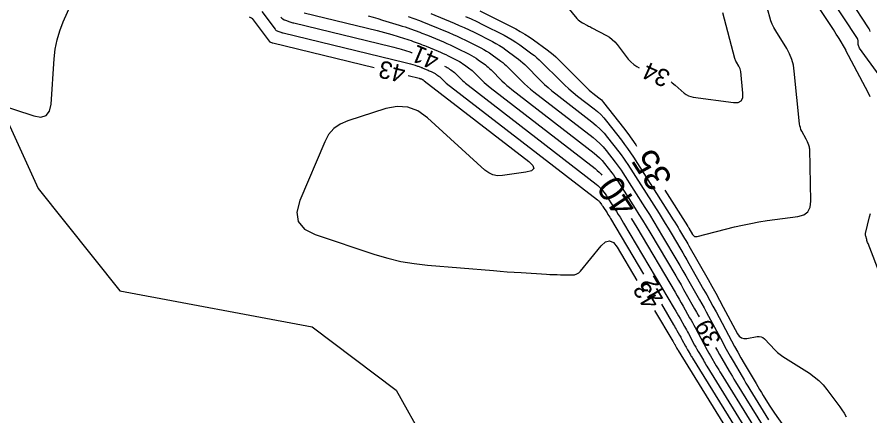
# Model space of a CAD drawing. Extents: x 2384780 to 2405861, y 547869 to 573706.
# Drawn here: x 2390194.3 to 2390291.8, y 552348.1 to 552393.7 of the extents above; entities that cross this region are included whole.
import ezdxf

# ---------------------------------------------------------------- set-up
doc = ezdxf.new("R2010")
doc.units = 0
for name, color, linetype in [('Old_Level_60', 7, 'Continuous'), ('Old_Level_61', 7, 'Continuous'), ('Prop Buffer Zone 1', 7, 'Continuous')]:
    doc.layers.add(name, color=color, linetype=linetype)

msp = doc.modelspace()

# ---------------------------------------------------------------- linework, layer by layer
at = {"layer": 'Old_Level_60'}
for points in [[(2390291.862, 552392.0805), (2390291.8245, 552392.235), (2390291.766, 552392.383), (2390291.68675, 552392.52425), (2390289.58125, 552395.76625), (2390289.148, 552396.47025), (2390288.75025, 552397.19275), (2390288.38825, 552397.93375), (2390288.06175, 552398.69325), (2390286.382, 552402.87975), (2390286.2985, 552403.07075), (2390286.2045, 552403.2555), (2390286.09925, 552403.43425), (2390285.983, 552403.607), (2390285.58575, 552404.16175), (2390285.4995, 552404.27975), (2390285.41075, 552404.39575), (2390285.31975, 552404.51), (2390285.2265, 552404.62275)], [(2390191.8935, 552383.839), (2390196.21325, 552382.43025), (2390197.0315, 552382.2875), (2390197.63425, 552382.463), (2390198.022, 552382.957), (2390198.1945, 552383.76925), (2390198.541, 552388.9505), (2390198.6625, 552390.049), (2390198.878, 552391.12425), (2390199.18775, 552392.1765), (2390199.59175, 552393.20525), (2390202.20475, 552399.098)], [(2390291.86625, 552384.6), (2390291.74275, 552384.873), (2390291.6145, 552385.1435), (2390291.48175, 552385.41175), (2390291.344, 552385.6775), (2390289.09575, 552389.92975), (2390289.08975, 552389.9425), (2390289.085, 552389.95575), (2390289.08175, 552389.9695), (2390289.0795, 552389.9835), (2390289.075, 552390.03), (2390289.0735, 552390.03975), (2390289.07075, 552390.049), (2390289.06725, 552390.05825), (2390289.0625, 552390.06675), (2390288.317, 552391.275), (2390288.1565, 552391.5335), (2390287.9945, 552391.791), (2390287.83125, 552392.0475), (2390287.66625, 552392.303), (2390284.72025, 552396.83875)], [(2390256.70725, 552395.53525), (2390258.333, 552393.585), (2390258.46975, 552393.4365), (2390258.619, 552393.30375), (2390258.781, 552393.187), (2390258.9555, 552393.08575), (2390259.54675, 552392.78125), (2390259.67325, 552392.71575), (2390259.79975, 552392.65), (2390259.926, 552392.58375), (2390260.052, 552392.51725), (2390261.7245, 552391.6325), (2390262.069, 552391.4265), (2390262.38525, 552391.18725), (2390262.67375, 552390.91475), (2390262.934, 552390.60925), (2390264.21225, 552388.938), (2390264.504, 552388.60325), (2390264.8315, 552388.315), (2390265.195, 552388.07375), (2390265.46225, 552387.94325)], [(2390292.88875, 552387.07025), (2390290.6635, 552390.18075), (2390290.6035, 552390.2785), (2390290.55925, 552390.38175), (2390290.531, 552390.49025), (2390290.5185, 552390.60425), (2390290.504, 552390.98575), (2390290.49575, 552391.06575), (2390290.47725, 552391.1425), (2390290.44825, 552391.216), (2390290.40875, 552391.28625), (2390287.2375, 552396.169)], [(2390222.3085, 552394.3815), (2390223.80925, 552392.364), (2390223.87725, 552392.285), (2390223.95425, 552392.21875), (2390224.0405, 552392.165), (2390224.136, 552392.1235)], [(2390220.86625, 552393.7505), (2390220.91775, 552393.72875)], [(2390220.91775, 552393.72875), (2390221.08625, 552393.6595), (2390221.12075, 552393.6425), (2390221.15225, 552393.6215), (2390221.18025, 552393.5965), (2390221.20525, 552393.567), (2390223.12925, 552390.98025), (2390223.16, 552390.9445), (2390223.195, 552390.9145), (2390223.234, 552390.89025), (2390223.27725, 552390.8715), (2390223.425, 552390.8195), (2390223.457, 552390.80875), (2390223.489, 552390.799), (2390223.52125, 552390.78975), (2390223.55375, 552390.7815), (2390235.1455, 552387.97725)], [(2390224.48925, 552393.7475), (2390224.59425, 552393.6255), (2390224.7135, 552393.523), (2390224.847, 552393.43975), (2390224.99475, 552393.37575), (2390225.5005, 552393.19825), (2390225.60925, 552393.1615), (2390225.71875, 552393.12775), (2390225.82925, 552393.0965), (2390225.9405, 552393.06825), (2390237.0975, 552390.369), (2390237.3855, 552390.297), (2390237.67225, 552390.221), (2390237.95775, 552390.14075), (2390238.24225, 552390.05625), (2390239.229, 552389.75525), (2390239.3975, 552389.7025), (2390239.49, 552389.67225)], [(2390234.46175, 552393.86625), (2390235.016, 552393.71925), (2390235.56775, 552393.56425), (2390236.1175, 552393.401), (2390238.02425, 552392.8195), (2390238.35, 552392.71775), (2390238.67425, 552392.61125), (2390238.997, 552392.50025), (2390239.31825, 552392.38475), (2390240.36475, 552391.99975), (2390240.58875, 552391.916), (2390240.8115, 552391.83025), (2390241.03375, 552391.742), (2390241.25475, 552391.65175)], [(2390239.028, 552393.81175), (2390240.32725, 552393.334), (2390240.605, 552393.23025), (2390240.88175, 552393.12375), (2390241.15725, 552393.01425), (2390241.432, 552392.902), (2390243.685, 552391.968), (2390244.16575, 552391.76325), (2390244.6425, 552391.55), (2390245.115, 552391.32775), (2390245.58375, 552391.0965), (2390247.3505, 552390.20475), (2390247.68425, 552390.0275), (2390248.01, 552389.837), (2390248.3275, 552389.6335), (2390248.637, 552389.4165), (2390249.6345, 552388.686), (2390249.84475, 552388.5255), (2390250.0485, 552388.35725), (2390250.24575, 552388.18125), (2390250.43625, 552387.99775), (2390251.993, 552386.43725), (2390252.33175, 552386.1085), (2390252.68025, 552385.791), (2390253.039, 552385.485), (2390253.4075, 552385.19025), (2390260.1775, 552379.9535), (2390260.5845, 552379.618), (2390260.968, 552379.25925), (2390261.32825, 552378.87725), (2390261.66525, 552378.472), (2390262.7285, 552377.1095), (2390262.95275, 552376.81475), (2390263.1695, 552376.51525), (2390263.37925, 552376.2105), (2390263.58175, 552375.9005), (2390266.0985, 552371.946), (2390266.61925, 552371.1205), (2390267.13325, 552370.29075), (2390267.64075, 552369.45725), (2390268.1415, 552368.61925), (2390269.7665, 552365.876), (2390270.1135, 552365.28725), (2390270.45775, 552364.69725), (2390270.7995, 552364.1055), (2390271.13875, 552363.5125), (2390272.36075, 552361.3645), (2390272.621, 552360.9035), (2390272.87825, 552360.4405), (2390273.13225, 552359.976), (2390273.38325, 552359.50975), (2390274.967, 552356.543), (2390275.2645, 552355.992), (2390275.56725, 552355.444), (2390275.8755, 552354.899), (2390276.189, 552354.35675), (2390277.2215, 552352.59075), (2390277.444, 552352.213), (2390277.6685, 552351.8365), (2390277.8955, 552351.46125), (2390278.1245, 552351.08775), (2390280.2565, 552347.6335)], [(2390241.609, 552394.1525), (2390244.3, 552393.03675), (2390244.874, 552392.7925), (2390245.4435, 552392.5375), (2390246.008, 552392.272), (2390246.56775, 552391.996), (2390248.678, 552390.93075), (2390249.07675, 552390.71925), (2390249.4655, 552390.49175), (2390249.845, 552390.2485), (2390250.2145, 552389.98925), (2390251.40575, 552389.11675), (2390251.657, 552388.92525), (2390251.9005, 552388.72425), (2390252.13575, 552388.51425), (2390252.36325, 552388.29475), (2390254.22275, 552386.431), (2390254.62725, 552386.03825), (2390255.04375, 552385.65925), (2390255.472, 552385.29375), (2390255.91225, 552384.94175), (2390260.05325, 552381.7385), (2390260.54275, 552381.335), (2390261.004, 552380.9035), (2390261.4375, 552380.444), (2390261.843, 552379.95625), (2390263.12175, 552378.3175), (2390263.3915, 552377.96325), (2390263.6525, 552377.60275), (2390263.9045, 552377.23625), (2390264.14825, 552376.8635), (2390267.7265, 552371.24075), (2390268.07925, 552370.68175), (2390268.42725, 552370.11975), (2390268.771, 552369.55525), (2390269.11, 552368.98775), (2390270.2105, 552367.13), (2390270.4455, 552366.73125), (2390270.67875, 552366.33175), (2390270.91, 552365.931), (2390271.13975, 552365.5295), (2390272.82925, 552362.55975), (2390273.18925, 552361.92225), (2390273.54475, 552361.28225), (2390273.896, 552360.64), (2390274.243, 552359.99525), (2390276.02275, 552356.66175), (2390276.3755, 552356.00825), (2390276.7345, 552355.3585), (2390277.1, 552354.712), (2390277.47175, 552354.06925), (2390278.8195, 552351.76375), (2390279.02125, 552351.42125), (2390279.22475, 552351.08), (2390279.4305, 552350.74), (2390279.63825, 552350.40125), (2390280.32, 552349.2965), (2390280.468, 552349.06125), (2390280.61975, 552348.82825), (2390280.77525, 552348.59775), (2390280.9345, 552348.36975), (2390283.79275, 552344.3515)], [(2390245.5825, 552393.8215), (2390246.2445, 552393.525), (2390246.901, 552393.21625), (2390247.55175, 552392.8955), (2390250.00525, 552391.657), (2390250.469, 552391.41075), (2390250.92125, 552391.1465), (2390251.36225, 552390.8635), (2390251.792, 552390.562), (2390253.177, 552389.54775), (2390253.46925, 552389.32475), (2390253.75225, 552389.09125), (2390254.026, 552388.847), (2390254.2905, 552388.592), (2390256.4525, 552386.42475), (2390256.92275, 552385.96825), (2390257.407, 552385.5275), (2390257.905, 552385.1025), (2390258.417, 552384.69325), (2390260.299, 552383.2375), (2390260.691, 552382.91425), (2390261.06075, 552382.5685), (2390261.408, 552382.20025), (2390261.73275, 552381.8095), (2390263.42875, 552379.636), (2390263.78625, 552379.16625), (2390264.1325, 552378.68825), (2390264.467, 552378.20225), (2390264.78975, 552377.70775), (2390269.3545, 552370.5355), (2390269.539, 552370.24275), (2390269.72125, 552369.94875), (2390269.901, 552369.65325), (2390270.0785, 552369.3565), (2390270.6545, 552368.384), (2390270.7775, 552368.1755), (2390270.8995, 552367.96625), (2390271.02075, 552367.7565), (2390271.14075, 552367.54625), (2390273.3305, 552363.69775), (2390273.77375, 552362.9125), (2390274.21175, 552362.12425), (2390274.64425, 552361.333), (2390275.07175, 552360.539)], [(2390269.10475, 552386.3075), (2390269.24225, 552386.2145), (2390269.57075, 552385.9505), (2390270.614, 552385.04025), (2390270.84625, 552384.86475), (2390271.09625, 552384.72825), (2390271.364, 552384.63075), (2390271.64925, 552384.5725), (2390276.24125, 552383.96525), (2390276.76175, 552383.97125), (2390277.116, 552384.1485), (2390277.30425, 552384.497), (2390277.3265, 552385.01675), (2390277.07675, 552387.512), (2390277.05125, 552387.67425), (2390277.00825, 552387.8305), (2390276.9475, 552387.98075), (2390276.86925, 552388.125), (2390276.5845, 552388.5865), (2390276.5275, 552388.687), (2390276.478, 552388.791), (2390276.4365, 552388.89825), (2390276.40275, 552389.00875), (2390275.01725, 552394.21275)], [(2390224.136, 552392.1235), (2390224.46275, 552392.009), (2390224.533, 552391.98525), (2390224.604, 552391.96325), (2390224.67525, 552391.94325), (2390224.747, 552391.92475), (2390238.6935, 552388.55075), (2390238.84725, 552388.5125), (2390239.00025, 552388.47175), (2390239.15275, 552388.429), (2390239.3045, 552388.38375), (2390239.83125, 552388.22325), (2390239.92125, 552388.195), (2390240.011, 552388.16575), (2390240.1, 552388.135), (2390240.18875, 552388.103), (2390240.47775, 552387.99675), (2390240.53975, 552387.97375), (2390240.60125, 552387.95), (2390240.6625, 552387.92575), (2390240.72375, 552387.90075), (2390241.225, 552387.69275), (2390241.332, 552387.64725), (2390241.43825, 552387.59975), (2390241.5435, 552387.55025), (2390241.64775, 552387.49875), (2390242.041, 552387.30025), (2390242.11525, 552387.261), (2390242.18775, 552387.2185), (2390242.25825, 552387.17325), (2390242.32725, 552387.125), (2390242.54925, 552386.96225), (2390242.596, 552386.92675), (2390242.64125, 552386.88925), (2390242.68525, 552386.85), (2390242.7275, 552386.80925), (2390243.074, 552386.462), (2390243.1495, 552386.38875), (2390243.227, 552386.318), (2390243.30675, 552386.25), (2390243.38875, 552386.1845), (2390260.6745, 552372.81325), (2390260.75125, 552372.75), (2390260.8235, 552372.6825), (2390260.8915, 552372.6105), (2390260.955, 552372.534), (2390261.15525, 552372.27725), (2390261.1975, 552372.22175), (2390261.2385, 552372.16525), (2390261.278, 552372.10775), (2390261.31625, 552372.0495), (2390261.7865, 552371.3105), (2390261.88675, 552371.15175), (2390261.9855, 552370.992), (2390262.083, 552370.83175), (2390262.1795, 552370.67075), (2390265.95475, 552364.297)], [(2390241.25475, 552391.65175), (2390243.07, 552390.89925), (2390243.45725, 552390.73425), (2390243.84125, 552390.5625), (2390244.22225, 552390.38325), (2390244.59975, 552390.19725), (2390246.02325, 552389.47875), (2390246.292, 552389.336), (2390246.5545, 552389.1825), (2390246.81025, 552389.01825), (2390247.0595, 552388.8435), (2390247.86325, 552388.255), (2390248.03275, 552388.12575), (2390248.19675, 552387.99025), (2390248.3555, 552387.8485), (2390248.509, 552387.7005), (2390249.76325, 552386.44325), (2390250.03625, 552386.1785), (2390250.317, 552385.92275), (2390250.606, 552385.67625), (2390250.903, 552385.43875), (2390260.30175, 552378.1685), (2390260.626, 552377.901), (2390260.93175, 552377.61525), (2390261.219, 552377.3105), (2390261.48775, 552376.9875), (2390262.33525, 552375.90125), (2390262.514, 552375.6665), (2390262.68675, 552375.42775), (2390262.854, 552375.18475), (2390263.01525, 552374.93775), (2390265.0045, 552371.81225), (2390265.428, 552371.14075), (2390265.84625, 552370.466), (2390266.259, 552369.788), (2390266.66625, 552369.1065), (2390269.63425, 552364.09575), (2390269.938, 552363.5805), (2390270.23925, 552363.064), (2390270.5385, 552362.546), (2390270.83525, 552362.027), (2390271.8015, 552360.32875), (2390272.00725, 552359.96425), (2390272.2105, 552359.59825), (2390272.30925, 552359.418)], [(2390243.17425, 552388.1245), (2390243.36825, 552388.0265), (2390243.5075, 552387.9525), (2390243.64325, 552387.87325), (2390243.77575, 552387.78825), (2390243.90475, 552387.69775), (2390244.3205, 552387.39325), (2390244.40825, 552387.32625), (2390244.49325, 552387.25625), (2390244.57525, 552387.183), (2390244.65475, 552387.10625), (2390245.30375, 552386.45575), (2390245.445, 552386.31875), (2390245.59025, 552386.18625), (2390245.73975, 552386.05875), (2390245.8935, 552385.936), (2390260.55025, 552374.59825), (2390260.7095, 552374.467), (2390260.85975, 552374.32675), (2390261.00075, 552374.17725), (2390261.1325, 552374.0185), (2390261.54875, 552373.48525), (2390261.63625, 552373.37), (2390261.72125, 552373.25275), (2390261.80325, 552373.1335), (2390261.8825, 552373.01225), (2390262.85925, 552371.47775), (2390263.06725, 552371.148), (2390263.2725, 552370.81675), (2390263.475, 552370.48375), (2390263.675, 552370.14925), (2390269.474, 552360.359), (2390269.63925, 552360.079), (2390269.803, 552359.798), (2390269.96575, 552359.5165), (2390270.12725, 552359.234), (2390270.6525, 552358.3105), (2390270.7645, 552358.11225), (2390270.875, 552357.91325), (2390270.98425, 552357.71375), (2390271.09225, 552357.51325), (2390271.79975, 552356.1875), (2390271.9315, 552355.9435), (2390272.06575, 552355.701), (2390272.20225, 552355.4595), (2390272.341, 552355.2195), (2390272.79825, 552354.4375), (2390272.8965, 552354.27025), (2390272.996, 552354.1035), (2390273.0965, 552353.9375), (2390273.198, 552353.772), (2390282.35925, 552338.92925)], [(2390239.0335, 552387.0365), (2390240.2895, 552386.73275), (2390240.309, 552386.72775), (2390240.3285, 552386.72275), (2390240.34775, 552386.71725), (2390240.367, 552386.7115), (2390240.43375, 552386.69125), (2390240.445, 552386.6875), (2390240.4565, 552386.68375), (2390240.46775, 552386.68), (2390240.479, 552386.676), (2390240.5155, 552386.6625), (2390240.52325, 552386.6595), (2390240.53125, 552386.6565), (2390240.539, 552386.6535), (2390240.54675, 552386.65025), (2390240.61025, 552386.624), (2390240.62375, 552386.61825), (2390240.63725, 552386.61225), (2390240.6505, 552386.606), (2390240.66375, 552386.5995), (2390240.7135, 552386.57425), (2390240.723, 552386.56925), (2390240.732, 552386.564), (2390240.741, 552386.55825), (2390240.74975, 552386.552), (2390240.77775, 552386.5315), (2390240.78375, 552386.527), (2390240.7895, 552386.52225), (2390240.795, 552386.51725), (2390240.8005, 552386.512), (2390240.84425, 552386.468), (2390240.85375, 552386.45875), (2390240.86375, 552386.45), (2390240.87375, 552386.44125), (2390240.88425, 552386.433), (2390252.81725, 552377.20225), (2390253.288, 552376.74475), (2390253.38975, 552376.386), (2390253.1225, 552376.126), (2390252.48625, 552375.96475), (2390249.8055, 552375.5985), (2390249.24925, 552375.57875), (2390248.72975, 552375.67625), (2390248.2465, 552375.89125), (2390247.8, 552376.22325), (2390241.2325, 552382.21525), (2390240.159, 552382.989), (2390239.0105, 552383.42025), (2390237.787, 552383.50875), (2390236.4885, 552383.255), (2390232.1235, 552381.86575), (2390231.25725, 552381.49225), (2390230.5295, 552380.96725), (2390229.93975, 552380.29075), (2390229.48825, 552379.4625), (2390226.64025, 552372.728), (2390226.292, 552371.4035), (2390226.46775, 552370.3155), (2390227.168, 552369.4645), (2390228.392, 552368.85025), (2390235.2365, 552366.567), (2390236.7125, 552366.12275), (2390238.207, 552365.76875), (2390239.72, 552365.505), (2390241.2515, 552365.3315), (2390248.783, 552364.70375), (2390249.57475, 552364.64), (2390250.367, 552364.5805), (2390251.15975, 552364.5255), (2390251.9525, 552364.475), (2390254.83825, 552364.29875), (2390255.24575, 552364.27625), (2390255.65375, 552364.2585), (2390256.06175, 552364.2455), (2390256.47, 552364.237), (2390257.804, 552364.2175), (2390258.07675, 552364.2415), (2390258.32325, 552364.32175), (2390258.5435, 552364.4585), (2390258.73775, 552364.6515), (2390261.102, 552367.53825), (2390261.59625, 552367.9935), (2390262.06575, 552368.122), (2390262.5105, 552367.924), (2390262.93025, 552367.3995), (2390265.18525, 552363.5925)], [(2390295.614, 552357.4845), (2390291.629, 552367.8285), (2390291.58725, 552367.94), (2390291.54775, 552368.052), (2390291.51025, 552368.16475), (2390291.47475, 552368.27825), (2390291.36275, 552368.65025), (2390291.344, 552368.73), (2390291.33625, 552368.81025), (2390291.3395, 552368.89075), (2390291.3535, 552368.9715), (2390291.80825, 552370.85775), (2390291.89875, 552371.263)], [(2390267.22375, 552360.151), (2390269.31375, 552356.6225), (2390269.34025, 552356.57725), (2390269.36675, 552356.532), (2390269.393, 552356.48675), (2390269.419, 552356.44125), (2390269.5035, 552356.2925), (2390269.5215, 552356.2605), (2390269.5395, 552356.2285), (2390269.557, 552356.19625), (2390269.5745, 552356.164), (2390269.6885, 552355.9505), (2390269.7095, 552355.91125), (2390269.73125, 552355.872), (2390269.75325, 552355.83325), (2390269.7755, 552355.7945), (2390269.84925, 552355.6685), (2390269.865, 552355.64175), (2390269.881, 552355.61475), (2390269.89725, 552355.588), (2390269.9135, 552355.5615), (2390283.8315, 552333.012)], [(2390267.99325, 552360.8555), (2390269.394, 552358.49075), (2390269.48975, 552358.328), (2390269.585, 552358.165), (2390269.67925, 552358.0015), (2390269.773, 552357.83775), (2390270.078, 552357.3015), (2390270.143, 552357.1865), (2390270.20725, 552357.071), (2390270.27075, 552356.955), (2390270.33325, 552356.8385), (2390270.744, 552356.069), (2390270.8205, 552355.9275), (2390270.8985, 552355.7865), (2390270.97775, 552355.6465), (2390271.05825, 552355.507), (2390271.32375, 552355.053), (2390271.38075, 552354.956), (2390271.4385, 552354.85925), (2390271.497, 552354.76275), (2390271.55575, 552354.66675), (2390283.09525, 552335.97075)], [(2390275.07175, 552360.539), (2390276.712, 552357.4665), (2390276.906, 552357.1945), (2390277.14675, 552357.018), (2390277.43425, 552356.937), (2390277.76825, 552356.95175), (2390278.9355, 552357.1565), (2390279.1765, 552357.17225), (2390279.39925, 552357.13125), (2390279.6035, 552357.03375), (2390279.78975, 552356.88), (2390281.02125, 552355.6115), (2390281.29225, 552355.34825), (2390281.57725, 552355.10275), (2390281.87675, 552354.87475), (2390282.19025, 552354.66425), (2390284.91975, 552352.94775), (2390285.483, 552352.55675), (2390286.003, 552352.11875), (2390286.48, 552351.63425), (2390286.9135, 552351.103), (2390288.38575, 552349.12125), (2390288.646, 552348.753), (2390288.88775, 552348.37375), (2390289.11125, 552347.98325)], [(2390274.1995, 552355.89275), (2390274.40025, 552355.52975), (2390274.651, 552355.08575), (2390274.90625, 552354.6445), (2390275.747, 552353.20625), (2390275.92825, 552352.89875), (2390276.111, 552352.592), (2390276.29575, 552352.28675), (2390276.4825, 552351.9825), (2390280.88675, 552344.8465)]]:
    msp.add_lwpolyline(points, dxfattribs=at)
at = {"layer": 'Old_Level_61'}
for points in [[(2390247.23475, 552394.4515), (2390251.33275, 552392.383), (2390251.86125, 552392.1025), (2390252.37675, 552391.801), (2390252.8795, 552391.4785), (2390253.36925, 552391.135), (2390254.9485, 552389.9785), (2390255.2815, 552389.7245), (2390255.604, 552389.45825), (2390255.916, 552389.17975), (2390256.2175, 552388.889), (2390259.36025, 552385.739), (2390259.55225, 552385.5525), (2390259.75, 552385.3725), (2390259.95325, 552385.199), (2390260.1625, 552385.032), (2390260.8545, 552384.4965), (2390260.99875, 552384.37775), (2390261.13475, 552384.2505), (2390261.26225, 552384.11525), (2390261.38175, 552383.9715), (2390263.6635, 552381.04725), (2390264.1445, 552380.41525), (2390264.61025, 552379.77225), (2390265.06025, 552379.11825), (2390265.152, 552378.9775)], [(2390268.37975, 552373.91975), (2390270.9825, 552369.83), (2390270.999, 552369.804), (2390271.01525, 552369.77775), (2390271.03125, 552369.7515), (2390271.047, 552369.725), (2390271.0985, 552369.638), (2390271.1095, 552369.6195), (2390271.12025, 552369.60075), (2390271.13125, 552369.582), (2390271.142, 552369.56325), (2390271.55275, 552368.841), (2390271.6515, 552368.711), (2390271.77125, 552368.63075), (2390271.912, 552368.6), (2390272.07425, 552368.619), (2390276.36575, 552369.7055), (2390277.28775, 552369.9255), (2390278.215, 552370.11925), (2390279.14725, 552370.28725), (2390280.0845, 552370.429), (2390283.60975, 552370.9125), (2390284.26875, 552371.0985), (2390284.73475, 552371.44925), (2390285.00775, 552371.9645), (2390285.08775, 552372.6445), (2390284.9595, 552378.60575), (2390284.951, 552378.728), (2390284.9305, 552378.8475), (2390284.89825, 552378.9645), (2390284.85425, 552379.07875), (2390284.69125, 552379.448), (2390284.6555, 552379.52675), (2390284.6185, 552379.605), (2390284.58025, 552379.6825), (2390284.5405, 552379.75925), (2390284.055, 552380.67725), (2390283.96125, 552380.877), (2390283.888, 552381.083), (2390283.83525, 552381.295), (2390283.80275, 552381.51325), (2390283.197, 552387.56025), (2390283.09075, 552388.24075), (2390282.91025, 552388.896), (2390282.6555, 552389.52625), (2390282.327, 552390.1315), (2390281.08, 552392.1525), (2390280.865, 552392.531), (2390280.67925, 552392.92225), (2390280.52275, 552393.326), (2390280.39575, 552393.74225), (2390280.02825, 552395.12275)], [(2390227.13375, 552394.2115), (2390235.5015, 552392.187), (2390235.92375, 552392.08175), (2390236.344, 552391.97), (2390236.76275, 552391.8525), (2390237.17975, 552391.7285)], [(2390237.17975, 552391.7285), (2390238.62675, 552391.2875), (2390238.87375, 552391.21), (2390239.11975, 552391.1295), (2390239.36475, 552391.04525), (2390239.6085, 552390.9575), (2390240.4025, 552390.6655), (2390240.57225, 552390.602), (2390240.7415, 552390.53675), (2390240.91, 552390.47), (2390241.07775, 552390.40125), (2390242.455, 552389.83025), (2390242.749, 552389.70525), (2390243.04025, 552389.57475), (2390243.32925, 552389.439), (2390243.61575, 552389.29775), (2390244.69575, 552388.7525), (2390244.89975, 552388.64425), (2390245.09875, 552388.52775), (2390245.293, 552388.40325), (2390245.482, 552388.27075), (2390246.09175, 552387.824), (2390246.2205, 552387.726), (2390246.345, 552387.62325), (2390246.4655, 552387.51575), (2390246.582, 552387.4035), (2390247.5335, 552386.4495), (2390247.7405, 552386.2485), (2390247.95375, 552386.0545), (2390248.173, 552385.8675), (2390248.39825, 552385.68725), (2390260.426, 552376.3835), (2390260.66775, 552376.184), (2390260.89575, 552375.971), (2390261.11, 552375.744), (2390261.201, 552375.63425)], [(2390264.54725, 552370.66075), (2390264.55925, 552370.6415), (2390264.867, 552370.136), (2390265.1705, 552369.628), (2390269.554, 552362.2275), (2390269.7885, 552361.82975), (2390270.02125, 552361.431), (2390270.252, 552361.03125), (2390270.48125, 552360.6305), (2390271.227, 552359.31975), (2390271.38575, 552359.03825), (2390271.54275, 552358.75575), (2390271.69775, 552358.47225), (2390271.851, 552358.18775), (2390272.8555, 552356.306), (2390273.0425, 552355.95975), (2390273.233, 552355.61525), (2390273.4265, 552355.27275), (2390273.6235, 552354.932), (2390274.2725, 552353.82175), (2390274.41225, 552353.5845), (2390274.5535, 552353.34775), (2390274.69625, 552353.112), (2390274.84025, 552352.87725), (2390281.623, 552341.88775)]]:
    msp.add_lwpolyline(points, dxfattribs=at)
at = {"layer": 'Prop Buffer Zone 1'}
for points in [[(2390184.22013, 552401.58568), (2390196.73675, 552374.10875)], [(2390196.73675, 552374.10875), (2390206.072, 552362.4065), (2390228.06175, 552358.2825), (2390237.65825, 552351.032), (2390240.90407, 552345.2038)]]:
    msp.add_lwpolyline(points, dxfattribs=at)

# ---------------------------------------------------------------- texts
at = {"layer": 'Old_Level_60'}
for s, rotation, p in [('41', 157.2112917, (2390242.733, 552389.4685)), ('43', 166.3996889, (2390238.86275, 552388.10675)), ('34', 155.8151, (2390269.169, 552387.4355)), ('42', 120.6394, (2390268.63275, 552361.73825)), ('43', 120.6394, (2390267.8715, 552361.01975)), ('39', 118.2011139, (2390274.88725, 552356.726))]:
    msp.add_text(s, height=2, rotation=rotation, dxfattribs=at).set_placement(p)
at = {"layer": 'Old_Level_61'}
for s, rotation, p in [('35', 122.54475, (2390269.36125, 552375.17725)), ('40', 123.9334139, (2390265.45475, 552372.1525))]:
    msp.add_text(s, height=3, rotation=rotation, dxfattribs=at).set_placement(p)

doc.saveas('drawing.dxf')
